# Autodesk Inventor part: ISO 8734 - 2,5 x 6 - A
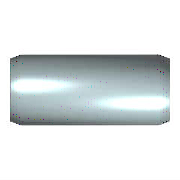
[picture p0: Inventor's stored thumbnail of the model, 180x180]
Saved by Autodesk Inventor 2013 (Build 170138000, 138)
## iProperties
IsCustomPart: 0
Created: 2012-02
Part Number: ISO 8734 - 2,5 x 6 - A
Material: Stahl
Description: Zylinderstifte aus gehärtetem Martensit-Edelstahl (Passstifte)
Document SubType Name: Modeling
Standard: ISO 8734
Designer: rYan
Standard Revision: Second edition 1997-11-15
Standards Organization: ISO
Language: de-DE
Size Designation: 2,5 x 6 - A
Categories: <MemberInstance><Categories><Category DisplayName="Verbindungselemente" InternalName="e4da775c-781d-43d5-af7c-5136215cf5a6" Mnemonic="FSTN"><Category DisplayNam
Density: 7.85 g/cm^3
Mass: 0.228634 g
Surface Area: 0.552727 cm^2
Volume: 0.0291253 cm^3
Author: rYan
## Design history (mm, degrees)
sketch "Skizze"
  geometry: C1 r 1.25 at (0, 0); 1 further point
  constraints: 1 centre point, 1 coincident
  dimensions: "d1" = 2.5 diameter of C1 (= NND)
extrude "Körper" new body sketch "Skizze" distance "d2" = 6 (= NLG); taper "d3" = 0 deg
chamfer "Skizze2" distance "d8" = 0.4 (= PHH); stored, may be unused: angle "d9" = 15 deg (= FAWI), second distance "d12" = 0.4 (= PHH)
body "Solid1"
chamfer "Fase1" distance "d4" = 0.4 (= PHH); stored, may be unused: angle "d5" = 15 deg (= FAWI), second distance "d11" = 0.4 (= PHH)
other parameters: "NND" = 2.5 [user parameter; used in 1 equation term], "NLG" = 6 [user parameter; used in 1 equation term], "PHH" = 0.4 [user parameter; used in 5 equation terms], "FAWI" = 15 deg [user parameter; used in 2 equation terms], "d13" = 0, "d15" = 0, "d16" = 0, "PHH2" = 0.4 (= PHH) [user parameter], "FAWI2" = 15 deg [user parameter]
